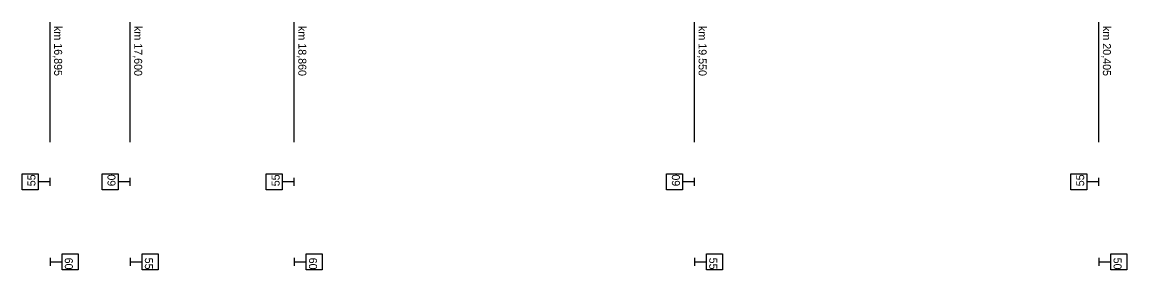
# Model space of a CAD drawing. Extents: x -1424 to 5155, y -2900 to 2050.
# Drawn here: x 4128 to 4404, y 1988 to 2050 of the extents above; entities that cross this region are included whole.
import ezdxf

# ---------------------------------------------------------------- set-up
doc = ezdxf.new("R2010")
doc.units = 0
doc.layers.add('rychlostník', color=7, linetype='Continuous')

msp = doc.modelspace()

# ---------------------------------------------------------------- linework, layer by layer
at = {"layer": 'rychlostník'}
for p, q in [((4135, 2020), (4135, 2050)), ((4135, 2020), (4135, 2050)), ((4155, 2020), (4155, 2050)), ((4155, 2020), (4155, 2050)), ((4196, 2020), (4196, 2050)), ((4196, 2020), (4196, 2050)), ((4296, 2020), (4296, 2050)), ((4296, 2020), (4296, 2050)), ((4397, 2020), (4397, 2050)), ((4397, 2020), (4397, 2050)), ((4128, 2008), (4128, 2012)), ((4128, 2012), (4132, 2012)), ((4130.33, 2010.09), (4130.33, 2010.09)), ((4132, 2012), (4132, 2008)), ((4135, 2010), (4132, 2010)), ((4135, 2009), (4135, 2011)), ((4148, 2008), (4148, 2012)), ((4148, 2012), (4152, 2012)), ((4150.33, 2010.09), (4150.33, 2010.09)), ((4152, 2012), (4152, 2008)), ((4155, 2010), (4152, 2010)), ((4155, 2009), (4155, 2011)), ((4189, 2008), (4189, 2012)), ((4189, 2012), (4193, 2012)), ((4191.33, 2010.09), (4191.33, 2010.09)), ((4193, 2012), (4193, 2008)), ((4196, 2010), (4193, 2010)), ((4196, 2009), (4196, 2011)), ((4289, 2008), (4289, 2012)), ((4289, 2012), (4293, 2012)), ((4291.33, 2010.09), (4291.33, 2010.09)), ((4293, 2012), (4293, 2008)), ((4296, 2010), (4293, 2010)), ((4296, 2009), (4296, 2011)), ((4390, 2008), (4390, 2012)), ((4390, 2012), (4394, 2012)), ((4392.33, 2010.09), (4392.33, 2010.09)), ((4394, 2012), (4394, 2008)), ((4397, 2010), (4394, 2010)), ((4397, 2009), (4397, 2011)), ((4132, 2008), (4128, 2008)), ((4152, 2008), (4148, 2008)), ((4193, 2008), (4189, 2008)), ((4293, 2008), (4289, 2008)), ((4394, 2008), (4390, 2008)), ((4135, 1991), (4135, 1989)), ((4135, 1990), (4138, 1990)), ((4138, 1992), (4142, 1992)), ((4138, 1988), (4138, 1992)), ((4142, 1992), (4142, 1988)), ((4155, 1991), (4155, 1989)), ((4155, 1990), (4158, 1990)), ((4158, 1992), (4162, 1992)), ((4158, 1988), (4158, 1992)), ((4162, 1992), (4162, 1988)), ((4196, 1991), (4196, 1989)), ((4196, 1990), (4199, 1990)), ((4199, 1992), (4203, 1992)), ((4199, 1988), (4199, 1992)), ((4203, 1992), (4203, 1988)), ((4296, 1991), (4296, 1989)), ((4296, 1990), (4299, 1990)), ((4299, 1992), (4303, 1992)), ((4299, 1988), (4299, 1992)), ((4303, 1992), (4303, 1988)), ((4397, 1991), (4397, 1989)), ((4397, 1990), (4400, 1990)), ((4400, 1992), (4404, 1992)), ((4400, 1988), (4400, 1992)), ((4404, 1992), (4404, 1988)), ((4142, 1988), (4138, 1988)), ((4139.67, 1989.91), (4139.67, 1989.91)), ((4162, 1988), (4158, 1988)), ((4159.67, 1989.91), (4159.67, 1989.91)), ((4203, 1988), (4199, 1988)), ((4200.67, 1989.91), (4200.67, 1989.91)), ((4303, 1988), (4299, 1988)), ((4300.67, 1989.91), (4300.67, 1989.91)), ((4404, 1988), (4400, 1988)), ((4401.67, 1989.91), (4401.67, 1989.91))]:
    msp.add_line(p, q, dxfattribs=at)

# ---------------------------------------------------------------- texts
for s, rotation, p in [('km 16,895', 270, (4136, 2049)), ('km 17,600', 270, (4156, 2049)), ('km 18,860', 270, (4197, 2049)), ('km 19,550', 270, (4297, 2049)), ('km 20,405', 270, (4398, 2049)), ('55', 90, (4131.33, 2008.93)), ('60', 90, (4151.33, 2008.93)), ('55', 90, (4192.33, 2008.93)), ('60', 90, (4292.33, 2008.93)), ('55', 90, (4393.33, 2008.93)), ('60', 270, (4138.67, 1991.07)), ('55', 270, (4158.67, 1991.07)), ('60', 270, (4199.67, 1991.07)), ('55', 270, (4299.67, 1991.07)), ('50', 270, (4400.67, 1991.07))]:
    msp.add_text(s, height=2, rotation=rotation, dxfattribs=at).set_placement(p)

doc.saveas('drawing.dxf')
